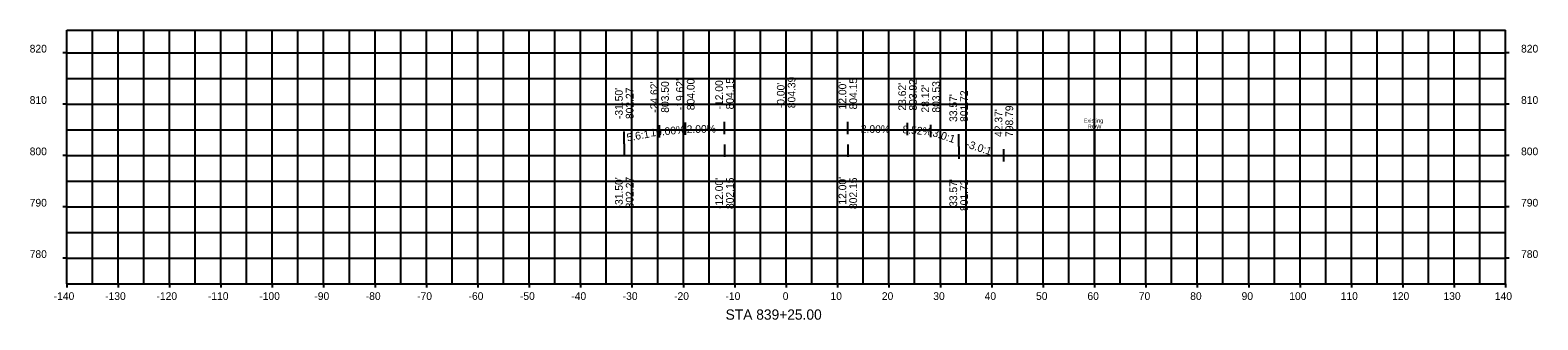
# Model space of a CAD drawing. Extents: x -147 to 146, y 768 to 824.
import ezdxf

# ---------------------------------------------------------------- set-up
doc = ezdxf.new("R2010")
doc.units = 0
for name, color, linetype in [('_CIVIL_CONSTRUCTION', 7, 'Continuous'), ('DisROW Existing', 7, 'Continuous'), ('ROW', 7, 'Continuous'), ('ROWLines', 7, 'Continuous'), ('SheetGridMinor', 7, 'Continuous'), ('Text', 7, 'Continuous')]:
    doc.layers.add(name, color=color, linetype=linetype)

msp = doc.modelspace()

# ---------------------------------------------------------------- linework, layer by layer
at = {"layer": '_CIVIL_CONSTRUCTION'}
for p, q in [((-140, 824.39), (140, 824.39)), ((-140, 775), (-140, 824.39)), ((140, 775), (140, 824.39)), ((-140, 775), (140, 775))]:
    msp.add_line(p, q, dxfattribs=at)
at = {"layer": 'DisROW Existing'}
for p, q in [((-130, 775), (-130, 824.39)), ((-120, 775), (-120, 824.39)), ((-110, 775), (-110, 824.39)), ((-100, 775), (-100, 824.39)), ((-90, 775), (-90, 824.39)), ((-80, 775), (-80, 824.39)), ((-70, 775), (-70, 824.39)), ((-60, 775), (-60, 824.39)), ((-50, 775), (-50, 824.39)), ((-40, 775), (-40, 824.39)), ((-30, 775), (-30, 824.39)), ((-20, 775), (-20, 824.39)), ((-10, 775), (-10, 824.39)), ((0, 775), (0, 824.39)), ((10, 775), (10, 824.39)), ((20, 775), (20, 824.39)), ((30, 775), (30, 824.39)), ((40, 775), (40, 824.39)), ((50, 775), (50, 824.39)), ((60, 775), (60, 824.39)), ((70, 775), (70, 824.39)), ((80, 775), (80, 824.39)), ((90, 775), (90, 824.39)), ((100, 775), (100, 824.39)), ((110, 775), (110, 824.39)), ((120, 775), (120, 824.39)), ((130, 775), (130, 824.39)), ((-140, 820), (-140.72, 820)), ((-140, 820), (140, 820)), ((140.72, 820), (140, 820)), ((-140, 810), (-140.72, 810)), ((-140, 810), (140, 810)), ((140.72, 810), (140, 810)), ((-140, 800), (-140.72, 800)), ((-140, 800), (140, 800)), ((140.72, 800), (140, 800)), ((-140, 790), (-140.72, 790)), ((-140, 790), (140, 790)), ((140.72, 790), (140, 790)), ((-140, 780), (-140.72, 780)), ((-140, 780), (140, 780)), ((140.72, 780), (140, 780)), ((-140, 775), (-140, 774.28)), ((-130, 775), (-130, 774.28)), ((-120, 775), (-120, 774.28)), ((-110, 775), (-110, 774.28)), ((-100, 775), (-100, 774.28)), ((-90, 775), (-90, 774.28)), ((-80, 775), (-80, 774.28)), ((-70, 775), (-70, 774.28)), ((-60, 775), (-60, 774.28)), ((-50, 775), (-50, 774.28)), ((-40, 775), (-40, 774.28)), ((-30, 775), (-30, 774.28)), ((-20, 775), (-20, 774.28)), ((-10, 775), (-10, 774.28)), ((0, 775), (0, 774.28)), ((10, 775), (10, 774.28)), ((20, 775), (20, 774.28)), ((30, 775), (30, 774.28)), ((40, 775), (40, 774.28)), ((50, 775), (50, 774.28)), ((60, 775), (60, 774.28)), ((70, 775), (70, 774.28)), ((80, 775), (80, 774.28)), ((90, 775), (90, 774.28)), ((100, 775), (100, 774.28)), ((110, 775), (110, 774.28)), ((120, 775), (120, 774.28)), ((130, 775), (130, 774.28)), ((140, 775), (140, 774.28))]:
    msp.add_line(p, q, dxfattribs=at)
at = {"layer": 'ROW'}
msp.add_line((60, 805.03), (60, 795.19), dxfattribs=at)
at = {"layer": 'SheetGridMinor'}
for p, q in [((-135, 775), (-135, 824.39)), ((-125, 775), (-125, 824.39)), ((-115, 775), (-115, 824.39)), ((-105, 775), (-105, 824.39)), ((-95, 775), (-95, 824.39)), ((-85, 775), (-85, 824.39)), ((-75, 775), (-75, 824.39)), ((-65, 775), (-65, 824.39)), ((-55, 775), (-55, 824.39)), ((-45, 775), (-45, 824.39)), ((-35, 775), (-35, 824.39)), ((-25, 775), (-25, 824.39)), ((-15, 775), (-15, 824.39)), ((-5, 775), (-5, 824.39)), ((5, 775), (5, 824.39)), ((15, 775), (15, 824.39)), ((25, 775), (25, 824.39)), ((35, 775), (35, 824.39)), ((45, 775), (45, 824.39)), ((55, 775), (55, 824.39)), ((65, 775), (65, 824.39)), ((75, 775), (75, 824.39)), ((85, 775), (85, 824.39)), ((95, 775), (95, 824.39)), ((105, 775), (105, 824.39)), ((115, 775), (115, 824.39)), ((125, 775), (125, 824.39)), ((135, 775), (135, 824.39)), ((-140, 815), (140, 815)), ((-140, 805), (140, 805)), ((-140, 795), (140, 795)), ((-140, 785), (140, 785))]:
    msp.add_line(p, q, dxfattribs=at)
at = {"layer": 'Text'}
for p, q in [((-31.5, 802.27), (-31.5, 804.67)), ((-31.5, 802.27), (-31.5, 804.67)), ((-24.62, 803.5), (-24.62, 805.9)), ((-24.62, 803.5), (-24.62, 805.9)), ((-19.62, 804), (-19.62, 806.4)), ((-19.62, 804), (-19.62, 806.4)), ((-12, 804.15), (-12, 806.55)), ((-12, 804.15), (-12, 806.55)), ((0, 804.39), (0, 806.79)), ((0, 804.39), (0, 806.79)), ((12, 804.15), (12, 806.55)), ((12, 804.15), (12, 806.55)), ((23.62, 803.92), (23.62, 806.32)), ((23.62, 803.92), (23.62, 806.32)), ((28.12, 803.53), (28.12, 805.93)), ((28.12, 803.53), (28.12, 805.93)), ((33.57, 801.72), (33.57, 804.12)), ((33.57, 801.72), (33.57, 804.12)), ((33.57, 801.72), (33.57, 804.12)), ((33.57, 801.72), (33.57, 804.12)), ((-31.5, 802.27), (-31.5, 799.87)), ((-31.5, 802.27), (-31.5, 799.87)), ((-12, 802.15), (-12, 799.75)), ((-12, 802.15), (-12, 799.75)), ((12, 802.15), (12, 799.75)), ((12, 802.15), (12, 799.75)), ((33.57, 801.72), (33.57, 799.32)), ((33.57, 801.72), (33.57, 799.32)), ((42.37, 798.79), (42.37, 801.19)), ((42.37, 798.79), (42.37, 801.19))]:
    msp.add_line(p, q, dxfattribs=at)

# ---------------------------------------------------------------- texts
at = {"layer": 'ROW'}
for s, p in [('Existing', (57.91, 806.38)), ('ROW', (58.69, 805.2))]:
    msp.add_text(s, height=0.787, dxfattribs=at).set_placement(p)
at = {"layer": 'ROWLines'}
for s, height, p in [('820', 1.5, (-147.2, 820.03)), ('820', 1.5, (143, 820.03)), ('810', 1.5, (-147.2, 810.03)), ('810', 1.5, (143, 810.03)), ('800', 1.5, (-147.2, 800.03)), ('800', 1.5, (143, 800.03)), ('790', 1.5, (-147.2, 790.03)), ('790', 1.5, (143, 790.03)), ('780', 1.5, (-147.2, 780.03)), ('780', 1.5, (143, 780.03)), ('-140', 1.5, (-142.53, 771.85)), ('-130', 1.5, (-132.53, 771.85)), ('-120', 1.5, (-122.53, 771.85)), ('-110', 1.5, (-112.53, 771.85)), ('-100', 1.5, (-102.53, 771.85)), ('-90', 1.5, (-91.81, 771.85)), ('-80', 1.5, (-81.81, 771.85)), ('-70', 1.5, (-71.81, 771.85)), ('-60', 1.5, (-61.81, 771.85)), ('-50', 1.5, (-51.81, 771.85)), ('-40', 1.5, (-41.81, 771.85)), ('-30', 1.5, (-31.81, 771.85)), ('-20', 1.5, (-21.81, 771.85)), ('-10', 1.5, (-11.81, 771.85)), ('0', 1.5, (-0.67, 771.85)), ('10', 1.5, (8.62, 771.85)), ('20', 1.5, (18.62, 771.85)), ('30', 1.5, (28.62, 771.85)), ('40', 1.5, (38.62, 771.85)), ('50', 1.5, (48.62, 771.85)), ('60', 1.5, (58.62, 771.85)), ('70', 1.5, (68.62, 771.85)), ('80', 1.5, (78.62, 771.85)), ('90', 1.5, (88.62, 771.85)), ('100', 1.5, (97.9, 771.85)), ('110', 1.5, (107.9, 771.85)), ('120', 1.5, (117.9, 771.85)), ('130', 1.5, (127.9, 771.85)), ('140', 1.5, (137.9, 771.85)), ('STA 839+25.00', 2.004, (-11.78, 768))]:
    msp.add_text(s, height=height, dxfattribs=at).set_placement(p)
at = {"layer": 'Text'}
for s, rotation, p in [("-31.50'", 90, (-31.8, 807.07)), ("-31.50'", 90, (-31.8, 807.07)), ('802.27', 90, (-29.7, 807.07)), ('802.27', 90, (-29.7, 807.07)), ("-24.62'", 90, (-24.92, 808.3)), ("-24.62'", 90, (-24.92, 808.3)), ('803.50', 90, (-22.82, 808.3)), ('803.50', 90, (-22.82, 808.3)), ("-19.62'", 90, (-19.92, 808.8)), ("-19.62'", 90, (-19.92, 808.8)), ('804.00', 90, (-17.82, 808.8)), ('804.00', 90, (-17.82, 808.8)), ("-12.00'", 90, (-12.3, 808.95)), ("-12.00'", 90, (-12.3, 808.95)), ('804.15', 90, (-10.2, 808.95)), ('804.15', 90, (-10.2, 808.95)), ("-0.00'", 90, (-0.3, 809.19)), ("-0.00'", 90, (-0.3, 809.19)), ('804.39', 90, (1.8, 809.19)), ('804.39', 90, (1.8, 809.19)), ("12.00'", 90, (11.7, 808.95)), ("12.00'", 90, (11.7, 808.95)), ('804.15', 90, (13.8, 808.95)), ('804.15', 90, (13.8, 808.95)), ("23.62'", 90, (23.32, 808.72)), ("23.62'", 90, (23.32, 808.72)), ('803.92', 90, (25.42, 808.72)), ('803.92', 90, (25.42, 808.72)), ("28.12'", 90, (27.82, 808.33)), ("28.12'", 90, (27.82, 808.33)), ('803.53', 90, (29.92, 808.33)), ('803.53', 90, (29.92, 808.33)), ("33.57'", 90, (33.27, 806.52)), ("33.57'", 90, (33.27, 806.52)), ("33.57'", 90, (33.27, 806.52)), ("33.57'", 90, (33.27, 806.52)), ('801.72', 90, (35.37, 806.52)), ('801.72', 90, (35.37, 806.52)), ('801.72', 90, (35.37, 806.52)), ('801.72', 90, (35.37, 806.52)), ("42.37'", 90, (42.07, 803.59)), ("42.37'", 90, (42.07, 803.59)), ('798.79', 90, (44.17, 803.59)), ('798.79', 90, (44.17, 803.59)), ('5.6:1', 10.1248, (-30.9, 802.71)), ('10.00%', 5.7106, (-26.35, 803.65)), ('2.00%', 1.1458, (-19.35, 804.33)), ('-2.00%', 358.8542, (13.84, 804.44)), ('-8.52%', 355.1321, (21.92, 804.39)), ('-3.0:1', 341.565, (27.72, 804)), ('-3.0:1', 341.565, (34.84, 801.63)), ("-31.50'", 90, (-31.8, 789.67)), ("-31.50'", 90, (-31.8, 789.67)), ('802.27', 90, (-29.7, 789.69)), ('802.27', 90, (-29.7, 789.69)), ("-12.00'", 90, (-12.3, 789.55)), ("-12.00'", 90, (-12.3, 789.55)), ('802.15', 90, (-10.2, 789.55)), ('802.15', 90, (-10.2, 789.55)), ("12.00'", 90, (11.7, 790.41)), ("12.00'", 90, (11.7, 790.41)), ('802.15', 90, (13.8, 789.55)), ('802.15', 90, (13.8, 789.55)), ("33.57'", 90, (33.27, 789.98)), ("33.57'", 90, (33.27, 789.98)), ('801.72', 90, (35.37, 789.16)), ('801.72', 90, (35.37, 789.16))]:
    msp.add_text(s, height=1.5, rotation=rotation, dxfattribs=at).set_placement(p)

doc.saveas('drawing.dxf')
